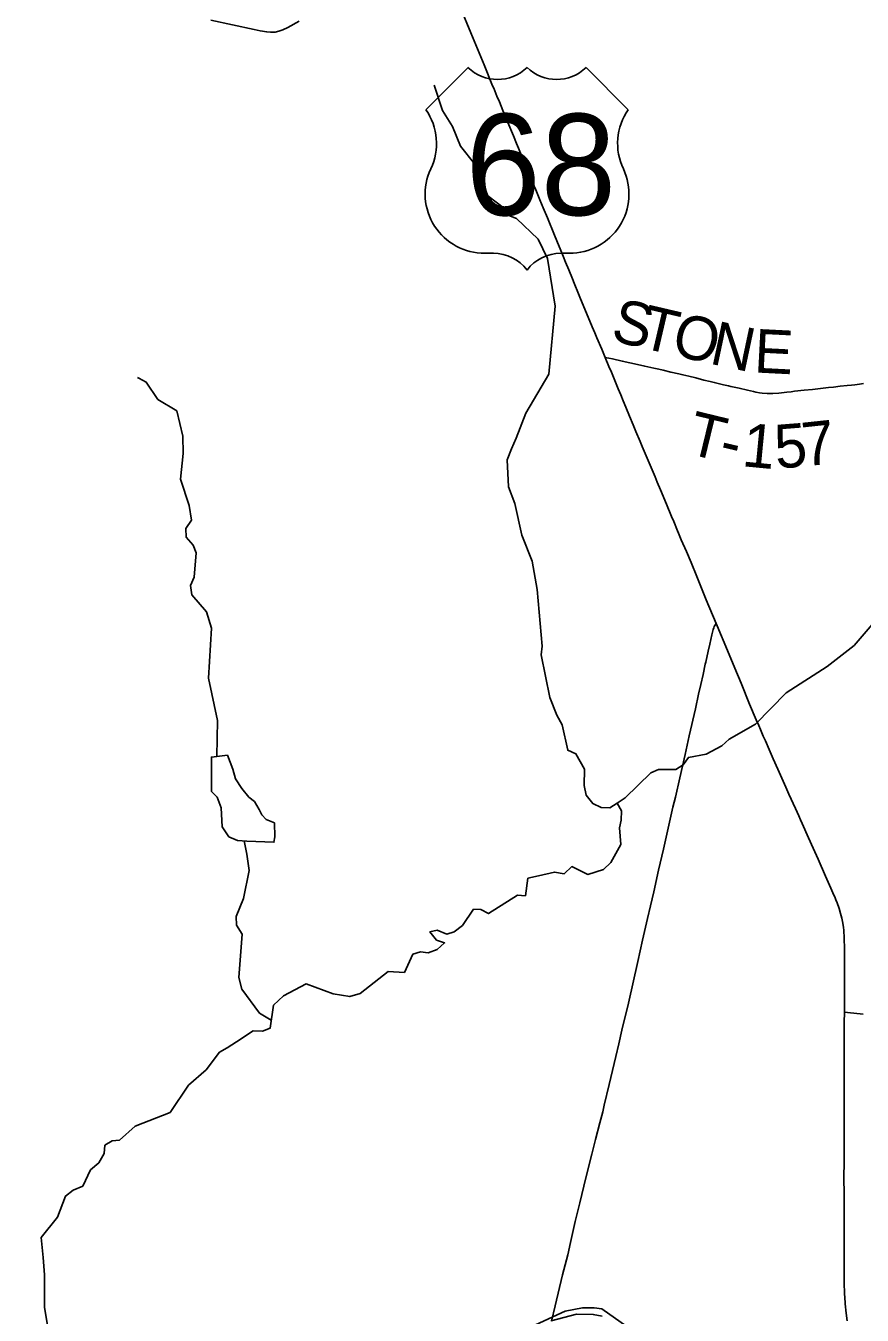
# Model space of a CAD drawing. Extents: x -1.4 to 35.4, y 0 to 22.
# Drawn here: x 13.85 to 14.939, y 15.116 to 16.794 of the extents above; entities that cross this region are included whole.
import ezdxf

# ---------------------------------------------------------------- set-up
doc = ezdxf.new("R2010")
doc.units = 0
for name, color, linetype in [('GM_X_County_Road', 7, 'Continuous'), ('GM_X_Major_River', 7, 'Continuous'), ('GM_X_Minor_Lake', 7, 'Continuous'), ('GM_X_Minor_River', 7, 'Continuous'), ('GM_X_Township_Road', 7, 'Continuous'), ('GM_X_Township_Road_Text', 7, 'Continuous'), ('GM_X_US_Location', 7, 'Continuous'), ('GM_X_US_Route', 7, 'Continuous'), ('GM_X_US_Shield', 7, 'Continuous'), ('SC_Scratch1', 7, 'Continuous')]:
    doc.layers.add(name, color=color, linetype=linetype)

msp = doc.modelspace()

# ---------------------------------------------------------------- linework, layer by layer
at = {"layer": 'GM_X_County_Road'}
msp.add_lwpolyline([(14.5347, 15.1076), (14.5396, 15.1278), (14.5494, 15.1682), (14.556, 15.194), (14.5597, 15.2103), (14.5659, 15.2375), (14.5718, 15.2616), (14.5795, 15.2942), (14.5873, 15.3251), (14.5924, 15.3443), (14.5979, 15.366), (14.6016, 15.3804), (14.6036, 15.3888), (14.6102, 15.4157), (14.6186, 15.452), (14.6226, 15.4689), (14.6267, 15.4865), (14.6353, 15.5216), (14.6475, 15.5757), (14.6533, 15.6036), (14.66, 15.6319), (14.6638, 15.6482), (14.6681, 15.6663), (14.6743, 15.6948), (14.6806, 15.7221), (14.6904, 15.765), (14.6931, 15.7765), (14.6963, 15.7896), (14.7022, 15.815), (14.7055, 15.8302), (14.7088, 15.8454), (14.7142, 15.8696), (14.7223, 15.9048), (14.7264, 15.9236), (14.7293, 15.9363), (14.7322, 15.9495), (14.7351, 15.9628), (14.7357, 15.9653), (14.7389, 15.9798), (14.741, 15.9889), (14.7437, 16.001), (14.7456, 16.0081), (14.7463, 16.01), (14.7469, 16.0116), (14.7493, 16.0157)], dxfattribs=at)
at = {"layer": 'GM_X_Major_River'}
msp.add_lwpolyline([(14.6402, 15.0958), (14.6006, 15.1237), (14.5904, 15.1251), (14.5752, 15.125), (14.5526, 15.1206), (14.4858, 15.0898)], dxfattribs=at)
at = {"layer": 'GM_X_Minor_Lake'}
for points in [[(14.1745, 15.738), (14.1741, 15.7562), (14.1635, 15.7606), (14.1579, 15.7667), (14.1542, 15.7736), (14.148, 15.784), (14.1409, 15.7898), (14.1316, 15.801), (14.1234, 15.8137), (14.1198, 15.8263), (14.1129, 15.8442), (14.092, 15.8419), (14.092, 15.7971), (14.0995, 15.7898), (14.1049, 15.776), (14.106, 15.7509), (14.1149, 15.7382), (14.1262, 15.7335), (14.1384, 15.7325)], [(14.1384, 15.7325), (14.1735, 15.7311), (14.1745, 15.738)]]:
    msp.add_lwpolyline(points, dxfattribs=at)
at = {"layer": 'GM_X_Minor_River'}
for points in [[(13.8732, 15.1906), (13.8706, 15.2165), (13.8919, 15.2431), (13.9023, 15.2706), (13.9119, 15.2784), (13.9245, 15.2835), (13.9347, 15.3046), (13.9455, 15.3139), (13.9526, 15.326), (13.9531, 15.3366), (13.9627, 15.3425), (13.9726, 15.3435), (13.9927, 15.3614), (14.0382, 15.3792), (14.0623, 15.4148), (14.0854, 15.435), (14.1025, 15.4578), (14.1125, 15.4637), (14.1248, 15.4711), (14.1463, 15.4856), (14.1584, 15.4853), (14.1684, 15.489), (14.1731, 15.5189), (14.1858, 15.5312), (14.2153, 15.5466), (14.2508, 15.5339), (14.2723, 15.5301), (14.2857, 15.534), (14.3223, 15.5627), (14.3435, 15.5615), (14.3545, 15.5853), (14.3645, 15.5885), (14.3743, 15.5872), (14.3862, 15.5916), (14.3958, 15.6001), (14.3852, 15.6037), (14.3767, 15.6145), (14.3862, 15.6166), (14.3987, 15.6115), (14.4082, 15.6144), (14.419, 15.6229), (14.4334, 15.6439), (14.4429, 15.6434), (14.453, 15.6383), (14.4906, 15.6623), (14.5009, 15.6614), (14.5043, 15.6841), (14.518, 15.6873), (14.539, 15.6922), (14.5515, 15.6901), (14.5615, 15.6994), (14.5822, 15.6892), (14.6025, 15.6957), (14.6121, 15.7046), (14.625, 15.728), (14.6235, 15.75), (14.6256, 15.7599), (14.6262, 15.772), (14.6203, 15.782), (14.6107, 15.7757), (14.5997, 15.7763), (14.5887, 15.7814), (14.5802, 15.7925), (14.5774, 15.8047), (14.5777, 15.826), (14.5667, 15.8459), (14.5561, 15.8507), (14.5487, 15.8838), (14.5417, 15.8965), (14.5326, 15.9194), (14.5214, 15.9751), (14.5228, 15.986), (14.5164, 16.0598), (14.5098, 16.0968), (14.4964, 16.1308), (14.4872, 16.172), (14.4788, 16.1934), (14.4772, 16.2287), (14.4827, 16.2431), (14.489, 16.257), (14.5017, 16.2894), (14.5315, 16.3402), (14.5398, 16.4289), (14.5299, 16.4906), (14.5174, 16.5159), (14.4894, 16.5426), (14.4792, 16.5465), (14.4699, 16.5588), (14.447, 16.5763), (14.4418, 16.603), (14.4351, 16.6137), (14.4166, 16.6368), (14.406, 16.6625), (14.3931, 16.6832), (14.3822, 16.7164)], [(14.0991, 15.8427), (14.1, 15.8896), (14.0884, 15.9445), (14.0922, 16.0098), (14.0857, 16.0308), (14.0664, 16.0531), (14.0647, 16.0653), (14.0698, 16.0758), (14.0722, 16.1077), (14.0682, 16.1176), (14.0593, 16.128), (14.0587, 16.1394), (14.0661, 16.1503), (14.0631, 16.1694), (14.0519, 16.2034), (14.0555, 16.2371), (14.0547, 16.2595), (14.0469, 16.2923), (14.0225, 16.3072), (14.0073, 16.3298), (13.9975, 16.3349), (13.9957, 16.3357)], [(14.6203, 15.782), (14.631, 15.789), (14.6642, 15.8215), (14.6742, 15.8259), (14.6966, 15.8255), (14.7062, 15.8318), (14.7132, 15.8415), (14.7364, 15.8457), (14.7567, 15.8563), (14.7664, 15.8653), (14.8005, 15.8848), (14.8403, 15.9255), (14.894, 15.9599), (14.929, 15.9871), (14.955, 16.0174)], [(14.17, 15.4993), (14.1547, 15.5086), (14.1316, 15.5397), (14.1277, 15.555), (14.1321, 15.6115), (14.1247, 15.623), (14.1245, 15.6344), (14.134, 15.6578), (14.1411, 15.6941), (14.1384, 15.7154), (14.1346, 15.7328)], [(13.9152, 14.8928), (13.8695, 14.9109), (13.8541, 14.9352), (13.8504, 14.9584), (13.8552, 14.991), (13.8693, 15.0248), (13.8773, 15.0471), (13.8809, 15.0895), (13.8748, 15.1254), (13.8746, 15.1679), (13.8732, 15.1906)]]:
    msp.add_lwpolyline(points, dxfattribs=at)
at = {"layer": 'GM_X_Township_Road'}
for points in [[(14.0912, 16.801), (14.1476, 16.7888), (14.1555, 16.7871), (14.1642, 16.7856), (14.1692, 16.7852), (14.1749, 16.7854), (14.1799, 16.7865), (14.1852, 16.7884), (14.1915, 16.7914), (14.2062, 16.7995)], [(14.6047, 16.362), (14.6144, 16.36), (14.6271, 16.3572), (14.6471, 16.3527), (14.6564, 16.3506), (14.6682, 16.348), (14.6745, 16.3467), (14.6804, 16.3453), (14.6905, 16.3429), (14.7008, 16.3406), (14.7061, 16.3394), (14.7136, 16.3376), (14.7227, 16.3354), (14.7334, 16.3326), (14.7413, 16.3307), (14.7468, 16.3294), (14.7588, 16.3264), (14.7655, 16.3249), (14.7685, 16.3242), (14.7794, 16.3218), (14.7903, 16.3193), (14.7981, 16.3175), (14.801, 16.3169), (14.8056, 16.3161), (14.8093, 16.3156), (14.8157, 16.3151), (14.8194, 16.315), (14.8231, 16.3151), (14.8311, 16.3156), (14.8415, 16.3167), (14.847, 16.3174), (14.8513, 16.3179), (14.8637, 16.3192), (14.8749, 16.3203), (14.8954, 16.3227), (14.9021, 16.3234), (14.9106, 16.3244), (14.9198, 16.3254), (14.9254, 16.326), (14.9297, 16.3265), (14.9358, 16.3272), (14.9411, 16.3279)], [(14.9163, 15.5101), (14.9202, 15.5096), (14.9406, 15.5074)]]:
    msp.add_lwpolyline(points, dxfattribs=at)
at = {"layer": 'GM_X_US_Route'}
for points in [[(14.9157, 15.2872), (14.9157, 15.2935), (14.9159, 15.3165), (14.9161, 15.3345), (14.9161, 15.3438), (14.9161, 15.3581), (14.9161, 15.3661), (14.9161, 15.3767), (14.9161, 15.3879), (14.9161, 15.3947), (14.9161, 15.3996), (14.9159, 15.4139), (14.9159, 15.423), (14.9161, 15.4309), (14.9162, 15.4402), (14.9162, 15.4483), (14.9161, 15.4637), (14.9161, 15.476), (14.9161, 15.4983), (14.9162, 15.5014), (14.9163, 15.5051), (14.9163, 15.5101), (14.9166, 15.5256), (14.9165, 15.5323), (14.9166, 15.5373), (14.9165, 15.5415), (14.9166, 15.5452), (14.9166, 15.5496), (14.9166, 15.5533), (14.9166, 15.5682), (14.9165, 15.5862), (14.9164, 15.5924), (14.9161, 15.606), (14.9156, 15.6165), (14.9152, 15.62), (14.9147, 15.6232), (14.9138, 15.6281), (14.9129, 15.6324), (14.9114, 15.6382), (14.9095, 15.6448), (14.9069, 15.652), (14.9053, 15.6559), (14.9042, 15.6588), (14.9014, 15.6651), (14.8987, 15.6713), (14.8917, 15.687), (14.882, 15.7088), (14.8755, 15.7235), (14.8697, 15.7366), (14.8614, 15.7553), (14.8591, 15.7604), (14.8568, 15.7655), (14.8525, 15.7751), (14.8441, 15.7938), (14.8401, 15.8029), (14.8298, 15.8261), (14.8237, 15.8397), (14.8185, 15.8517), (14.8135, 15.863), (14.8107, 15.8692), (14.807, 15.8778), (14.8049, 15.8829), (14.8016, 15.8903), (14.7929, 15.9109), (14.7817, 15.9379), (14.7736, 15.9574), (14.764, 15.9806), (14.7506, 16.0127), (14.7493, 16.0157), (14.7365, 16.0466), (14.7242, 16.0767), (14.7166, 16.0951), (14.7105, 16.1094), (14.7039, 16.1248), (14.7003, 16.1334), (14.6991, 16.1362), (14.6941, 16.1483), (14.6912, 16.1551), (14.6846, 16.1712), (14.677, 16.1896), (14.6727, 16.1998), (14.6698, 16.2067), (14.6659, 16.2158), (14.662, 16.225), (14.6581, 16.2341), (14.6531, 16.2461), (14.6505, 16.2524), (14.6449, 16.2656), (14.6414, 16.2742), (14.6366, 16.2856), (14.6319, 16.2971), (14.6284, 16.3057), (14.6253, 16.3132), (14.6219, 16.3212), (14.6164, 16.3343), (14.613, 16.343), (14.6096, 16.3503), (14.6047, 16.362), (14.6039, 16.3641), (14.6003, 16.3727), (14.5941, 16.3875), (14.5913, 16.3938), (14.588, 16.4018), (14.572, 16.4402), (14.5702, 16.4448), (14.5645, 16.4586), (14.5621, 16.4643), (14.5573, 16.4758), (14.553, 16.4861), (14.5499, 16.4936), (14.5386, 16.5212), (14.5295, 16.5436), (14.5239, 16.5568), (14.5197, 16.5671), (14.5144, 16.5803), (14.5125, 16.585), (14.5104, 16.5901), (14.5021, 16.6102), (14.4964, 16.6236), (14.492, 16.6342), (14.4893, 16.6405), (14.4854, 16.6503), (14.4782, 16.6675), (14.4751, 16.6749), (14.4714, 16.6835), (14.467, 16.6944), (14.4639, 16.7019), (14.4597, 16.7122), (14.4583, 16.7156), (14.4473, 16.7426), (14.4297, 16.7845), (14.4171, 16.8149)], [(14.92, 15.1082), (14.9186, 15.118), (14.9173, 15.1303), (14.9172, 15.1322), (14.9164, 15.1439), (14.916, 15.1576), (14.916, 15.188), (14.9159, 15.2091), (14.9159, 15.2317), (14.9159, 15.247), (14.9159, 15.2718), (14.9158, 15.2799), (14.9157, 15.2872)]]:
    msp.add_lwpolyline(points, dxfattribs=at)
at = {"layer": 'GM_X_US_Shield'}
for p, q in [((14.4262, 16.7393), (14.3713, 16.6844)), ((14.6349, 16.6844), (14.58, 16.7393)), ((14.4482, 16.4976), (14.4592, 16.4976)), ((14.547, 16.4976), (14.558, 16.4976))]:
    msp.add_line(p, q, dxfattribs=at)
for centre, radius, start, end in [((14.4646, 16.7786), 0.0549, 225.573, 314.427), ((14.5416, 16.7786), 0.0549, 225.573, 314.427), ((14.3083, 16.6403), 0.0769, 334.5471, 35.0009), ((14.6979, 16.6403), 0.0769, 144.9991, 205.4529), ((14.4473, 16.5745), 0.0769, 154.8319, 270.6383), ((14.5589, 16.5745), 0.0769, 269.3617, 25.1681), ((14.4592, 16.4427), 0.0549, 36.8699, 90), ((14.547, 16.4427), 0.0549, 90, 143.1301)]:
    msp.add_arc(centre, radius, start, end, dxfattribs=at)
at = {"layer": 'SC_Scratch1'}
for points in [[(14.6009, 15.1141), (14.5892, 15.1165), (14.5675, 15.1167), (14.5345, 15.1081)], [(14.5345, 15.1081), (14.5675, 15.1167), (14.5892, 15.1165), (14.6009, 15.1141)]]:
    msp.add_lwpolyline(points, dxfattribs=at)

# ---------------------------------------------------------------- texts
at = {"layer": 'GM_X_Township_Road_Text'}
for s, rotation, p in [('S', 346.8223, (14.6105, 16.3843)), ('T', 346.8213, (14.6479, 16.3755)), ('O', 346.8262, (14.6892, 16.3659)), ('N', 347.9743, (14.7391, 16.3542)), ('E', 357.0864, (14.7978, 16.3425)), ('T', 346.3099, (14.709, 16.2375)), ('7', 6.1146, (14.864, 16.2201)), ('1', 354.5126, (14.7817, 16.2206)), ('5', 4.5371, (14.8274, 16.2172)), ('-', 346.7717, (14.7508, 16.2273))]:
    msp.add_text(s, height=0.0568, rotation=rotation, dxfattribs=at).set_placement(p)
at = {"layer": 'GM_X_US_Location'}
for s in ['0', '/']:
    msp.add_text(s, height=0.000189, dxfattribs=at).set_placement((14.503, 16.612))
msp.add_text('68', height=0.000189, rotation=0, dxfattribs=at).set_placement((14.4639, 16.5728))
at = {"layer": 'GM_X_US_Shield'}
msp.add_text('68', height=0.13184, dxfattribs=at).set_placement((14.4229, 16.5471))

doc.saveas('drawing.dxf')
